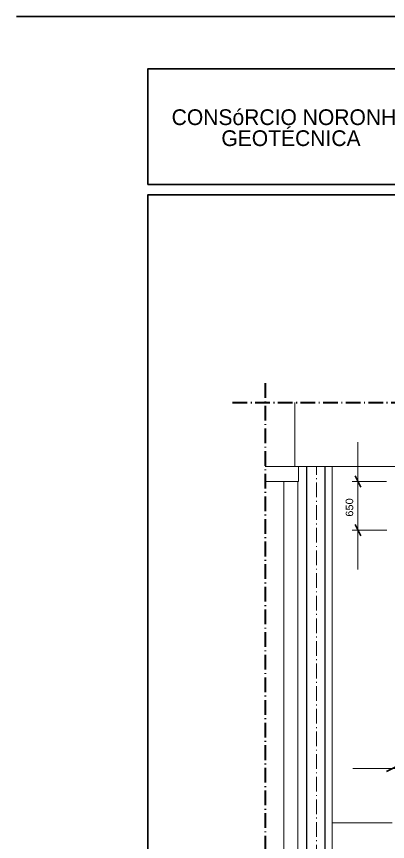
# Model space of a CAD drawing. Extents: x -4160 to -2690, y -474 to 714.
# Drawn here: x -3739.8 to -3669.1, y -333.7 to -176.5 of the extents above; entities that cross this region are included whole.
import ezdxf
from ezdxf.enums import TextEntityAlignment as Align

# ---------------------------------------------------------------- set-up
doc = ezdxf.new("R2010")
doc.units = 0
doc.header["$LTSCALE"] = 0.56
doc.linetypes.add('DOT_DASHED', pattern=[7.7, 5, -1.2, 0.3, -1.2])
for name, color, linetype, lineweight in [('11', 7, 'Continuous', 13), ('13', 7, 'Continuous', 13), ('2', 7, 'Continuous', 25), ('5', 7, 'Continuous', 35), ('63', 7, 'Continuous', 13), ('7', 7, 'DOT_DASHED', 13), ('9', 7, 'Continuous', 13)]:
    doc.layers.add(name, color=color, linetype=linetype, lineweight=lineweight)

msp = doc.modelspace()

# ---------------------------------------------------------------- linework, layer by layer
at = {"layer": '11'}
for p, q in [((-3692.4141, -262.287), (-3686.0327, -262.287)), ((-3686.0327, -262.287), (-3686.0327, -265.1441)), ((-3679.6041, -262.287), (-3655.3184, -262.287)), ((-3692.4141, -265.1441), (-3686.0327, -265.1441))]:
    msp.add_line(p, q, dxfattribs=at)
msp.add_lwpolyline([(-3679.6041, -354.3712), (-3679.6041, -287.7526), (-3679.6041, -262.287)], dxfattribs=at)
at = {"layer": '13'}
for p, q in [((-3686.0327, -262.287), (-3679.6041, -262.287)), ((-3688.8327, -287.7526), (-3688.8327, -265.1441)), ((-3688.8327, -386.7754), (-3688.8327, -287.7526))]:
    msp.add_line(p, q, dxfattribs=at)
msp.add_lwpolyline([(-3686.1555, -354.3712), (-3686.1555, -287.7526), (-3686.1555, -265.1441)], dxfattribs=at)
at = {"layer": '2', "lineweight": 13}
for p, q in [((-3674.7312, -281.9041), (-3674.7312, -257.6442)), ((-3669.2469, -265.1442), (-3675.8026, -265.1442)), ((-3669.2241, -274.4042), (-3675.8026, -274.4042)), ((-3675.6755, -319.8141), (-3641.4212, -319.8141))]:
    msp.add_line(p, q, dxfattribs=at)
at = {"layer": '2', "lineweight": 35}
for p, q in [((-3674.1955, -266.2156), (-3675.2669, -264.0727)), ((-3675.2669, -273.3327), (-3674.1955, -275.4756)), ((-3667.1041, -319.2784), (-3669.2469, -320.3498))]:
    msp.add_line(p, q, dxfattribs=at)
at = {"layer": '5', "linetype": 'DOT_DASHED', "lineweight": 13}
msp.add_line((-3682.604, -354.3712), (-3682.604, -262.287), dxfattribs=at)
at = {"layer": '5', "lineweight": 25}
for points in [[(-3739.7642, -176.52), (-3529.7642, -176.52), (-3739.7642, -176.52)], [(-3739.764, -176.52), (-3529.7642, -176.52), (-3529.7642, -473.5197)]]:
    msp.add_lwpolyline(points, dxfattribs=at)
at = {"layer": '5'}
for points in [[(-3714.764, -208.5199), (-3714.764, -186.52), (-3659.7641, -186.52), (-3659.7641, -208.5199)], [(-3714.764, -463.5197), (-3714.764, -210.5199), (-3540.7642, -210.5199), (-3540.7642, -463.5197)]]:
    msp.add_lwpolyline(points, close=True, dxfattribs=at)
at = {"layer": '63'}
for p, q in [((-3686.747, -250.077), (-3686.747, -262.287)), ((-3668.1756, -330.144), (-3679.6041, -330.144))]:
    msp.add_line(p, q, dxfattribs=at)
at = {"layer": '7', "linetype": 'Continuous'}
msp.add_line((-3692.4141, -262.287), (-3690.557, -262.287), dxfattribs=at)
at = {"layer": '9', "linetype": 'DOT_DASHED', "lineweight": 40}
for p, q in [((-3692.4141, -246.3984), (-3692.4141, -446.0525)), ((-3698.5912, -250.077), (-3552.9457, -250.077))]:
    msp.add_line(p, q, dxfattribs=at)
at = {"layer": '9'}
for points in [[(-3684.547, -262.287), (-3684.547, -287.7526), (-3684.547, -354.3712)], [(-3684.4613, -262.287), (-3684.4613, -287.7526), (-3684.4613, -354.3712)], [(-3681.0327, -262.287), (-3681.0327, -287.7526), (-3681.0327, -354.3712)], [(-3680.947, -354.3712), (-3680.947, -287.7526), (-3680.947, -262.287)]]:
    msp.add_lwpolyline(points, dxfattribs=at)

# ---------------------------------------------------------------- texts
at = {"layer": '2', "width": 1.1}
msp.add_text('650', height=1.429, rotation=90, dxfattribs=at).set_placement((-3675.6212, -270.0713), align=Align.CENTER)
at = {"layer": '5'}
for s, p in [('CONSóRCIO NORONHA', (-3687.4748, -197.2042)), ('GEOTÉCNICA', (-3687.4748, -201.2042))]:
    msp.add_text(s, height=3, dxfattribs=at).set_placement(p, align=Align.CENTER)

doc.saveas('drawing.dxf')
